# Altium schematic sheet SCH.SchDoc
size A3; PageSetup: Record=PageOptions¦CenterHorizontal=True¦CenterVertical=True¦PrintScale=1.00¦XCorrection=1.00¦YCorrection=1.00¦PrintKind=1¦BorderSize=5000000¦LeftOffset=0¦BottomOffset=0¦Orientation=2¦PaperLength=1000¦PaperWidth=1000¦Scale=100¦PaperSource=7¦PrintQuality=-4¦MediaType=1¦DitherType=10¦PrintScaleMode=1¦PaperKind=16K 197x273 mm¦PaperIndex=121
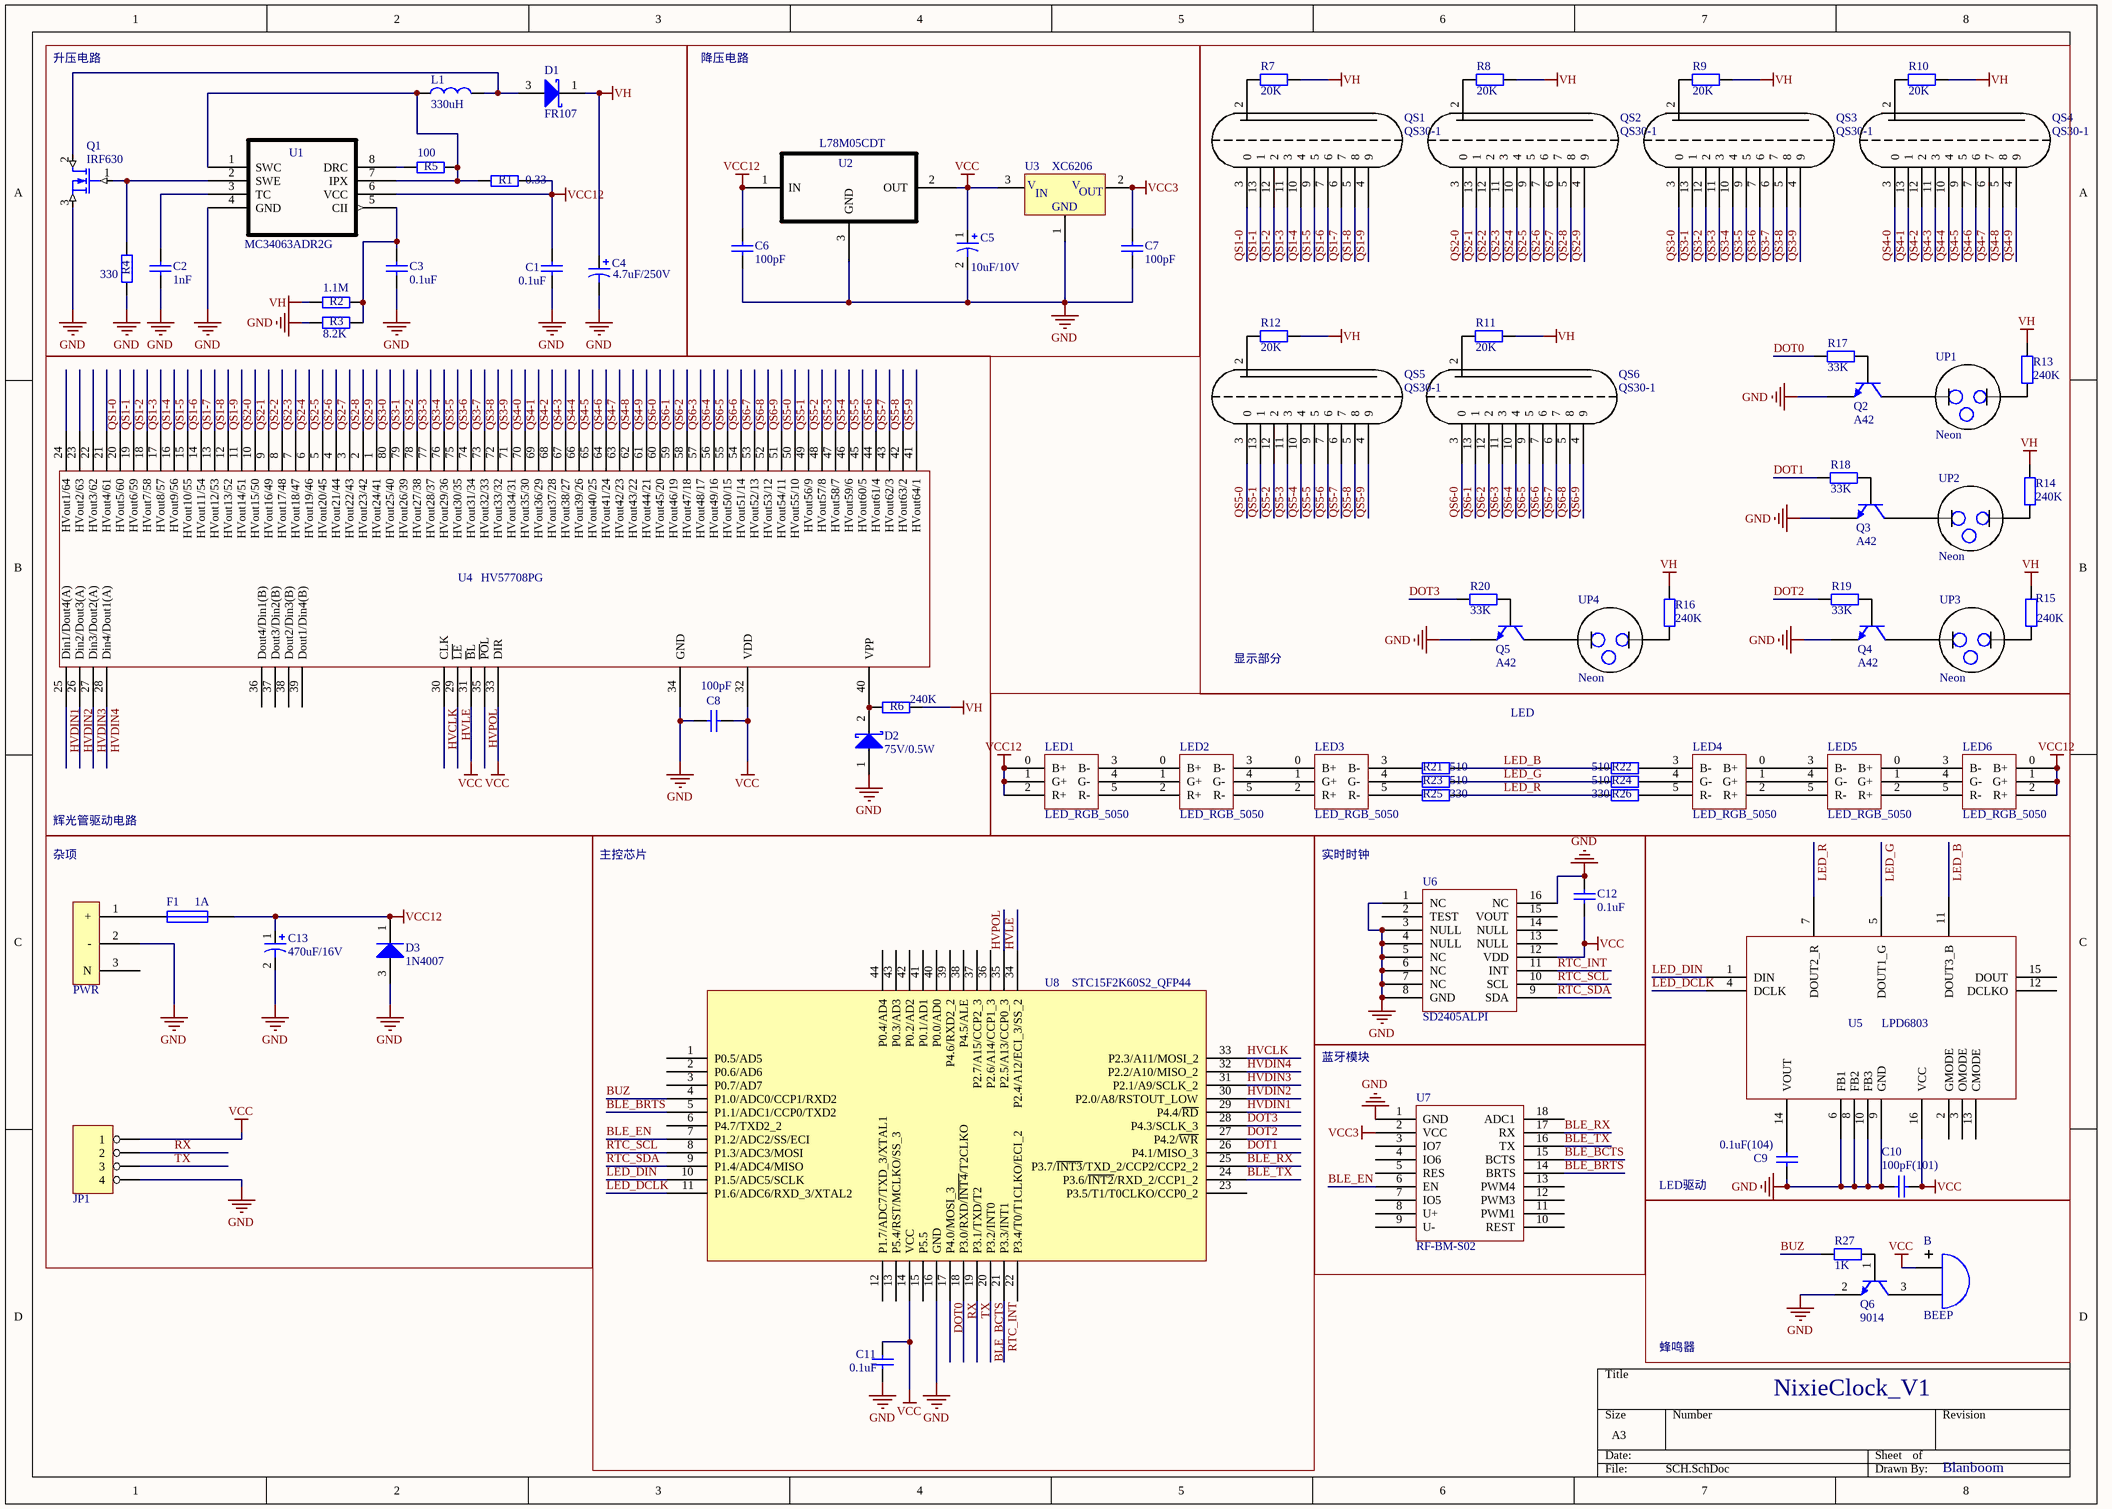
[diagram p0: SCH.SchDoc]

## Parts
B  BEEP  [BEEP]
C1  value 0.1uF  [0805]  (hidden comment: Cap)
C2  value 1nF  [0805]  (hidden comment: Cap)
C3  value 0.1uF  [0805]  (hidden comment: Cap)
C4  value 4.7uF/250V  [1812]  (hidden comment: Cap Pol3)
C5  value 10uF/10V  [1206_Diode]  (hidden comment: Cap Pol1)
C6  value 100pF  [0805]  (hidden comment: Cap)
C7  value 100pF  [0805]  (hidden comment: Cap)
C8  value 100pF  [0805]  (hidden comment: Cap)
C9  value 0.1uF(104)  [0805]  (hidden comment: Cap)
C10  value 100pF(101)  [0805]  (hidden comment: Cap)
C11  value 0.1uF  [0805]  (hidden comment: Cap)
C12  value 0.1uF  [0805]  (hidden comment: Cap)
C13  value 470uF/16V  [7343]  (hidden comment: Cap Pol1)
D1  FR107  [DO-214AC]
D2  75V/0.5W  [1206_Diode]
D3  1N4007  [DO-214AC]
F1  1A  [1206]
JP1  Header4  [HEADER4]  (value not drawn)
L1  330uH  [330uH]
LED1  LED_RGB_5050  [LED_RGB_5050]
LED2  LED_RGB_5050  [LED_RGB_5050]
LED3  LED_RGB_5050  [LED_RGB_5050]
LED4  LED_RGB_5050  [LED_RGB_5050]
LED5  LED_RGB_5050  [LED_RGB_5050]
LED6  LED_RGB_5050  [LED_RGB_5050]
PWR  PWR  [DC-044]  (value not drawn)
Q1  IRF630  [TO-263]
Q2  A42  [SOT-23-BJT]
Q3  A42  [SOT-23-BJT]
Q4  A42  [SOT-23-BJT]
Q5  A42  [SOT-23-BJT]
Q6  9014  [SOT-23-BJT]
QS1  QS30-1  [QS30-1]
QS2  QS30-1  [QS30-1]
QS3  QS30-1  [QS30-1]
QS4  QS30-1  [QS30-1]
QS5  QS30-1  [QS30-1]
QS6  QS30-1  [QS30-1]
R1  value 0.33  [0805]  (hidden comment: Res2)
R2  value 1.1M  [0805]  (hidden comment: Res2)
R3  value 8.2K  [0805]  (hidden comment: Res2)
R4  value 330  [0805]  (hidden comment: Res2)
R5  value 100  [0805]  (hidden comment: Res2)
R6  value 240K  [0805]  (hidden comment: Res2)
R7  value 20K  [0805]  (hidden comment: Res2)
R8  value 20K  [0805]  (hidden comment: Res2)
R9  value 20K  [0805]  (hidden comment: Res2)
R10  value 20K  [0805]  (hidden comment: Res2)
R11  value 20K  [0805]  (hidden comment: Res2)
R12  value 20K  [0805]  (hidden comment: Res2)
R13  value 240K  [0805]  (hidden comment: Res2)
R14  value 240K  [0805]  (hidden comment: Res2)
R15  value 240K  [0805]  (hidden comment: Res2)
R16  value 240K  [0805]  (hidden comment: Res2)
R17  value 33K  [0805]  (hidden comment: Res2)
R18  value 33K  [0805]  (hidden comment: Res2)
R19  value 33K  [0805]  (hidden comment: Res2)
R20  value 33K  [0805]  (hidden comment: Res2)
R21  value 510  [0805]  (hidden comment: Res2)
R22  value 510  [0805]  (hidden comment: Res2)
R23  value 510  [0805]  (hidden comment: Res2)
R24  value 510  [0805]  (hidden comment: Res2)
R25  value 330  [0805]  (hidden comment: Res2)
R26  value 330  [0805]  (hidden comment: Res2)
R27  value 1K  [0805]  (hidden comment: Res2)
U1  MC34063ADR2G  [SO-8-M]
U2  L78M05CDT  [DPAK-M]
U3  XC6206  [SOT-23]
U4  HV57708PG  [PQFP80]
U5  LPD6803  [SO-16]
U6  SD2405ALPI  [DIP16]
U7  RF-BM-S02  [RF-BM-S02]
U8  STC15F2K60S2_QFP44  [LQFP44]
UP1  Neon  [Neon]
UP2  Neon  [Neon]
UP3  Neon  [Neon]
UP4  Neon  [Neon]

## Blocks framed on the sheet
升压电路: C1-C4 D1 L1 Q1 R1-R5 U1
降压电路: C5-C7 U2 U3
显示部分: Q2-Q5 QS1-QS6 R7-R20 UP1-UP4
辉光管驱动电路: C8 D2 R6 U4
LED: LED1-LED6 R21-R26
主控芯片: C11 U8
实时时钟: C12 U6
LED驱动: C9 C10 U5
蓝牙模块: U7

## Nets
GND: C1.1 C2.1 C3.1 C4.2 C5.2 C6.1 C7.1 C8.1 C9.1 C10.1 C11.2 C12.2 C13.2 D2.1(A) D3.3(A) JP1.4 PWR.2(-) Q1.3(S) Q2.2(E) Q3.2(E) Q4.2(E) Q5.2(E) Q6.2(E) R3.1 R4.1 U1.4(GND) U2.3(GND) U3.1(GND) U4.34(GND) U5.6(FB1) U5.8(FB2) U5.9(GND) U5.10(FB3) U6.1(NC) U6.3(NULL) U6.4(NULL) U6.5(NC) U6.6(NC) U6.7(NC) U6.8(GND) U6.16(NC) U7.1(GND) U8.16(GND)
VCC: B.1(A) C5.1 C8.2 C10.2 C11.1 C12.1 JP1.1 U2.2(OUT) U3.3(VIN) U4.31(~{B}L) U4.32(VDD) U4.33(DIR) U5.16(VCC) U6.12(VDD) U8.14(VCC)
VCC3: C7.2 U3.2(VOUT) U7.2(VCC)
VCC12: C1.2 C6.2 C13.1 D3.1(K) F1.2 LED1.0(B+) LED1.1(G+) LED1.2(R+) LED6.0(B+) LED6.1(G+) LED6.2(R+) R1.2 U1.6(VCC) U2.1(IN)
VH: C4.1 D1.1(K) R2.1 R6.2 R7.2 R8.2 R9.2 R10.2 R11.2 R12.2 R13.1 R14.1 R15.1 R16.1
BLE_BCTS: U7.15(BCTS) U8.20(P3.2/INT0)
BLE_BRTS: U7.14(BRTS) U8.5(P1.1/ADC1/CCP0/TXD2)
BLE_EN: U7.6(EN) U8.7(P1.2/ADC2/SS/ECI)
BLE_RX: U7.17(RX) U8.25(P3.7/~{INT3}/TXD_2/CCP2/CCP2_2)
BLE_TX: U7.16(TX) U8.24(P3.6/~{INT2}/RXD_2/CCP1_2)
BUZ: R27.1 U8.4(P1.0/ADC0/CCP1/RXD2)
DOT0: R17.1 U8.17(P4.0/MOSI_3)
DOT1: R18.1 U8.26(P4.1/MISO_3)
DOT2: R19.1 U8.27(P4.2/~{WR})
DOT3: R20.1 U8.28(P4.3/SCLK_3)
HVCLK: U4.30(CLK) U8.33(P2.3/A11/MOSI_2)
HVDIN1: U4.25(Din1/Dout4(A)) U8.29(P4.4/~{RD})
HVDIN2: U4.26(Din2/Dout3(A)) U8.30(P2.0/A8/RSTOUT_LOW)
HVDIN3: U4.27(Din3/Dout2(A)) U8.31(P2.1/A9/SCLK_2)
HVDIN4: U4.28(Din4/Dout1(A)) U8.32(P2.2/A10/MISO_2)
HVLE: U4.29(~{LE}) U8.34(P2.4/A12/ECI_3/SS_2)
HVPOL: U4.35(~{PO}L) U8.35(P2.5/A13/CCP0_3)
LED_B: R21.2 R22.1 U5.11(DOUT3_B)
LED_DCLK: U5.4(DCLK) U8.11(P1.6/ADC6/RXD_3/XTAL2)
LED_DIN: U5.1(DIN) U8.10(P1.5/ADC5/SCLK)
LED_G: R23.2 R24.1 U5.5(DOUT1_G)
LED_R: R25.2 R26.1 U5.7(DOUT2_R)
QS1-0: QS1.3(0) U4.20(HVout5/60)
QS1-1: QS1.13(1) U4.19(HVout6/59)
QS1-2: QS1.12(2) U4.18(HVout7/58)
QS1-3: QS1.11(3) U4.17(HVout8/57)
QS1-4: QS1.10(4) U4.16(HVout9/56)
QS1-5: QS1.9(5) U4.15(HVout10/55)
QS1-6: QS1.7(6) U4.14(HVout11/54)
QS1-7: QS1.6(7) U4.13(HVout12/53)
QS1-8: QS1.5(8) U4.12(HVout13/52)
QS1-9: QS1.4(9) U4.11(HVout14/51)
QS2-0: QS2.3(0) U4.10(HVout15/50)
QS2-1: QS2.13(1) U4.9(HVout16/49)
QS2-2: QS2.12(2) U4.8(HVout17/48)
QS2-3: QS2.11(3) U4.7(HVout18/47)
QS2-4: QS2.10(4) U4.6(HVout19/46)
QS2-5: QS2.9(5) U4.5(HVout20/45)
QS2-6: QS2.7(6) U4.4(HVout21/44)
QS2-7: QS2.6(7) U4.3(HVout22/43)
QS2-8: QS2.5(8) U4.2(HVout23/42)
QS2-9: QS2.4(9) U4.1(HVout24/41)
QS3-0: QS3.3(0) U4.80(HVout25/40)
QS3-1: QS3.13(1) U4.79(HVout26/39)
QS3-2: QS3.12(2) U4.78(HVout27/38)
QS3-3: QS3.11(3) U4.77(HVout28/37)
QS3-4: QS3.10(4) U4.76(HVout29/36)
QS3-5: QS3.9(5) U4.75(HVout30/35)
QS3-6: QS3.7(6) U4.74(HVout31/34)
QS3-7: QS3.6(7) U4.73(HVout32/33)
QS3-8: QS3.5(8) U4.72(HVout33/32)
QS3-9: QS3.4(9) U4.71(HVout34/31)
QS4-0: QS4.3(0) U4.70(HVout35/30)
QS4-1: QS4.13(1) U4.69(HVout36/29)
QS4-2: QS4.12(2) U4.68(HVout37/28)
QS4-3: QS4.11(3) U4.67(HVout38/27)
QS4-4: QS4.10(4) U4.66(HVout39/26)
QS4-5: QS4.9(5) U4.65(HVout40/25)
QS4-6: QS4.7(6) U4.64(HVout41/24)
QS4-7: QS4.6(7) U4.63(HVout42/23)
QS4-8: QS4.5(8) U4.62(HVout43/22)
QS4-9: QS4.4(9) U4.61(HVout44/21)
QS5-0: QS5.3(0) U4.50(HVout55/10)
QS5-1: QS5.13(1) U4.49(HVout56/9)
QS5-2: QS5.12(2) U4.48(HVout57/8)
QS5-3: QS5.11(3) U4.47(HVout58/7)
QS5-4: QS5.10(4) U4.46(HVout59/6)
QS5-5: QS5.9(5) U4.45(HVout60/5)
QS5-6: QS5.7(6) U4.44(HVout61/4)
QS5-7: QS5.6(7) U4.43(HVout62/3)
QS5-8: QS5.5(8) U4.42(HVout63/2)
QS5-9: QS5.4(9) U4.41(HVout64/1)
QS6-0: QS6.3(0) U4.60(HVout45/20)
QS6-1: QS6.13(1) U4.59(HVout46/19)
QS6-2: QS6.12(2) U4.58(HVout47/18)
QS6-3: QS6.11(3) U4.57(HVout48/17)
QS6-4: QS6.10(4) U4.56(HVout49/16)
QS6-5: QS6.9(5) U4.55(HVout50/15)
QS6-6: QS6.7(6) U4.54(HVout51/14)
QS6-7: QS6.6(7) U4.53(HVout52/13)
QS6-8: QS6.5(8) U4.52(HVout53/12)
QS6-9: QS6.4(9) U4.51(HVout54/11)
RTC_INT: U6.11(INT) U8.21(P3.3/INT1)
RTC_SCL: U6.10(SCL) U8.8(P1.3/ADC3/MOSI)
RTC_SDA: U6.9(SDA) U8.9(P1.4/ADC4/MISO)
RX: JP1.2 U8.18(P3.0/RXD/~{INT4}/T2CLKO)
TX: JP1.3 U8.19(P3.1/TXD/T2)
NetB_2: B.2(B) Q6.3(C)
NetC2_2: C2.2 U1.3(TC)
NetC3_2: C3.2 R2.2 R3.2 U1.5(CII)
NetC9_2: C9.2 U5.14(VOUT)
NetD1_3: D1.3(A) L1.1 Q1.2(D)
NetD2_2: D2.2(K) R6.1 U4.40(VPP)
NetF1_1: F1.1 PWR.1(+)
NetL1_2: L1.2 R1.1 R5.1 U1.1(SWC) U1.7(IPX)
NetLED1_3: LED1.3(B-) LED2.0(B+)
NetLED1_4: LED1.4(G-) LED2.1(G+)
NetLED1_5: LED1.5(R-) LED2.2(R+)
NetLED2_3: LED2.3(B-) LED3.0(B+)
NetLED2_4: LED2.4(G-) LED3.1(G+)
NetLED2_5: LED2.5(R-) LED3.2(R+)
NetLED3_3: LED3.3(B-) R21.1
NetLED3_4: LED3.4(G-) R23.1
NetLED3_5: LED3.5(R-) R25.1
NetLED4_0: LED4.0(B+) LED5.3(B-)
NetLED4_1: LED4.1(G+) LED5.4(G-)
NetLED4_2: LED4.2(R+) LED5.5(R-)
NetLED4_3: LED4.3(B-) R22.2
NetLED4_4: LED4.4(G-) R24.2
NetLED4_5: LED4.5(R-) R26.2
NetLED5_0: LED5.0(B+) LED6.3(B-)
NetLED5_1: LED5.1(G+) LED6.4(G-)
NetLED5_2: LED5.2(R+) LED6.5(R-)
NetQ1_1: Q1.1(G) R4.2 U1.2(SWE)
NetQ2_1: Q2.1(B) R17.2
NetQ2_3: Q2.3(C) UP1.2
NetQ3_1: Q3.1(B) R18.2
NetQ3_3: Q3.3(C) UP2.2
NetQ4_1: Q4.1(B) R19.2
NetQ4_3: Q4.3(C) UP3.2
NetQ5_1: Q5.1(B) R20.2
NetQ5_3: Q5.3(C) UP4.2
NetQ6_1: Q6.1(B) R27.2
NetQS1_2: QS1.2 R7.1
NetQS2_2: QS2.2 R8.1
NetQS3_2: QS3.2 R9.1
NetQS4_2: QS4.2 R10.1
NetQS5_2: QS5.2 R12.1
NetQS6_2: QS6.2 R11.1
NetR5_2: R5.2 U1.8(DRC)
NetR13_2: R13.2 UP1.1
NetR14_2: R14.2 UP2.1
NetR15_2: R15.2 UP3.1
NetR16_2: R16.2 UP4.1

Not connected (* = marked no-connect by the designer): PWR 3(N); U4 21(HVout4/61) 22(HVout3/62) 23(HVout2/63) 24(HVout1/64) 36(Dout4/Din1(B)) 37(Dout3/Din2(B)) 38(Dout2/Din3(B)) 39(Dout1/Din4(B)); U5 2(GMODE) 3(OMODE) 12(DCLKO) 13(CMODE) 15(DOUT); U6 2(TEST) 13(NULL) 14(NULL) 15(VOUT); U7 3(IO7) 4(IO6) 5(RES) 7(IO5) 8(U+) 9(U-) 10(REST) 11(PWM1) 12(PWM3) 13(PWM4) 18(ADC1); U8 1(P0.5/AD5) 2(P0.6/AD6) 3(P0.7/AD7) 6(P4.7/TXD2_2) 12(P1.7/ADC7/TXD_3/XTAL1) 13(P5.4/RST/MCLKO/SS_3) 15(P5.5) 22(P3.4/T0/T1CLKO/ECI_2) 23(P3.5/T1/T0CLKO/CCP0_2) 36(P2.6/A14/CCP1_3) 37(P2.7/A15/CCP2_3) 38(P4.5/ALE) 39(P4.6/RXD2_2) 40(P0.0/AD0) 41(P0.1/AD1) 42(P0.2/AD2) 43(P0.3/AD3) 44(P0.4/AD4)

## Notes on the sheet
- 杂项
- 蜂鸣器
- NixieClock_V1
- Blanboom

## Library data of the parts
C1-C3 C6-C12 = Cap: Capacitor
C4 = Cap Pol3: Polarized Capacitor (Surface Mount)
C5 C13 = Cap Pol1: Polarized Capacitor (Radial)
D1 = Diode 18TQ045: Schottky Rectifier; Note: Terminal 2 is the TAB and is electrically connected to the cathode
D2 = Diode 10TQ040: Schottky Rectifier; Note: Terminal 2 is the TAB and is electrically connected to the cathode
D3 = Diode: Default Diode
F1 = Fuse 1: Fuse
JP1 = 4 HEADER: 4 Pin Header
L1 = L
PWR = header2
Q1 = IRF630: N-Channel MOSFET
Q2-Q6 = 2N3904: NPN General Purpose Amplifier
R1-R27 = Res2: Resistor
U1 = MC34063ACD-TR: Imported
U2 = L78M05CDT: Imported
U3 = XC6206: 3-Terminal Positive Voltage Regulator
